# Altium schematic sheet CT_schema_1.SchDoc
size 515 x 463 mm
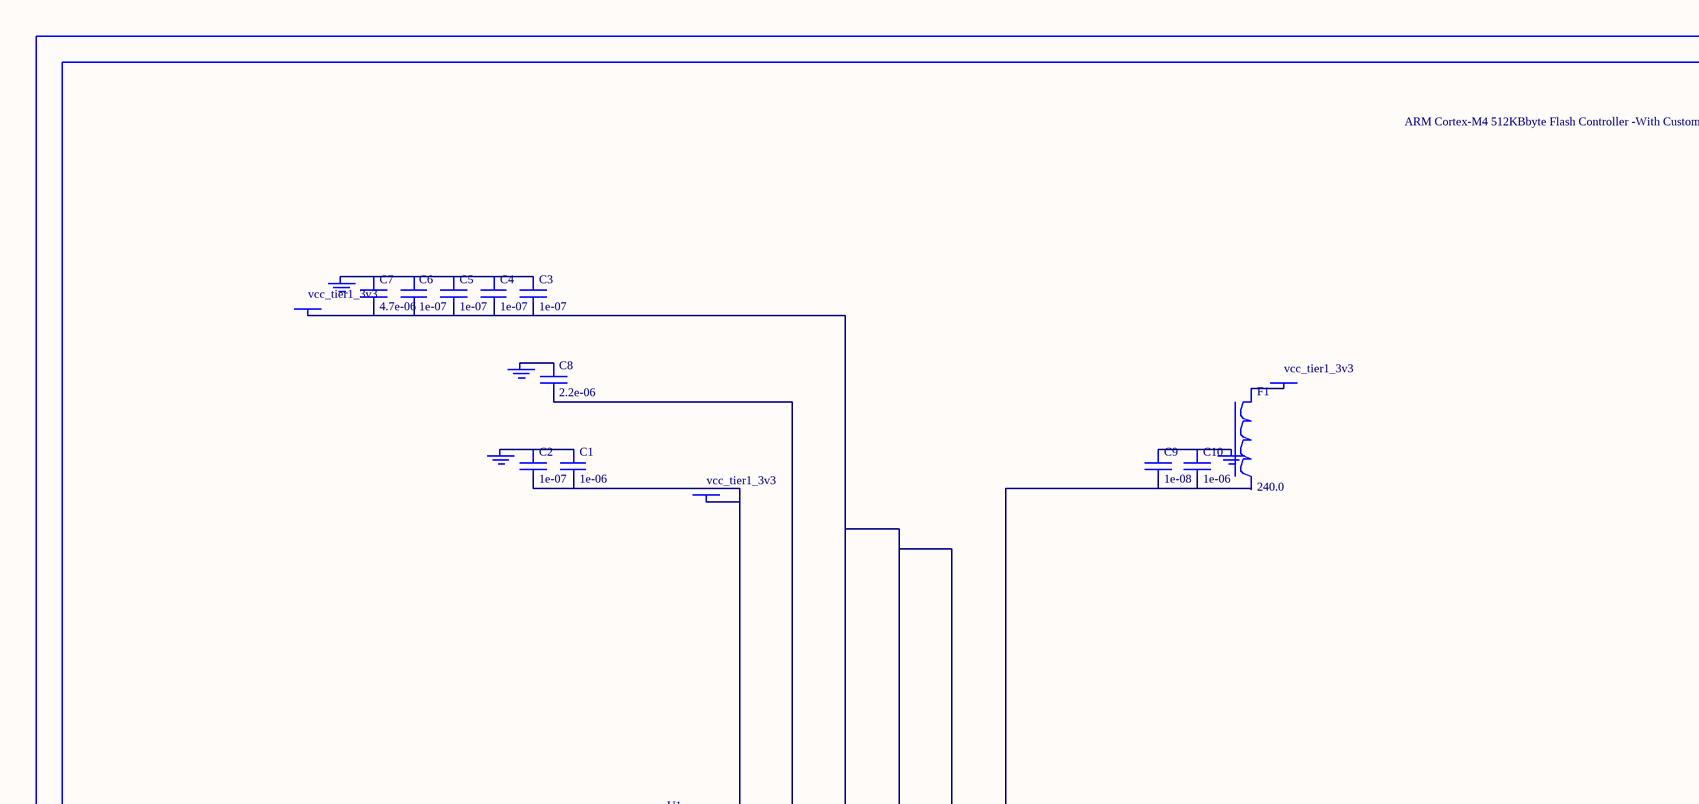
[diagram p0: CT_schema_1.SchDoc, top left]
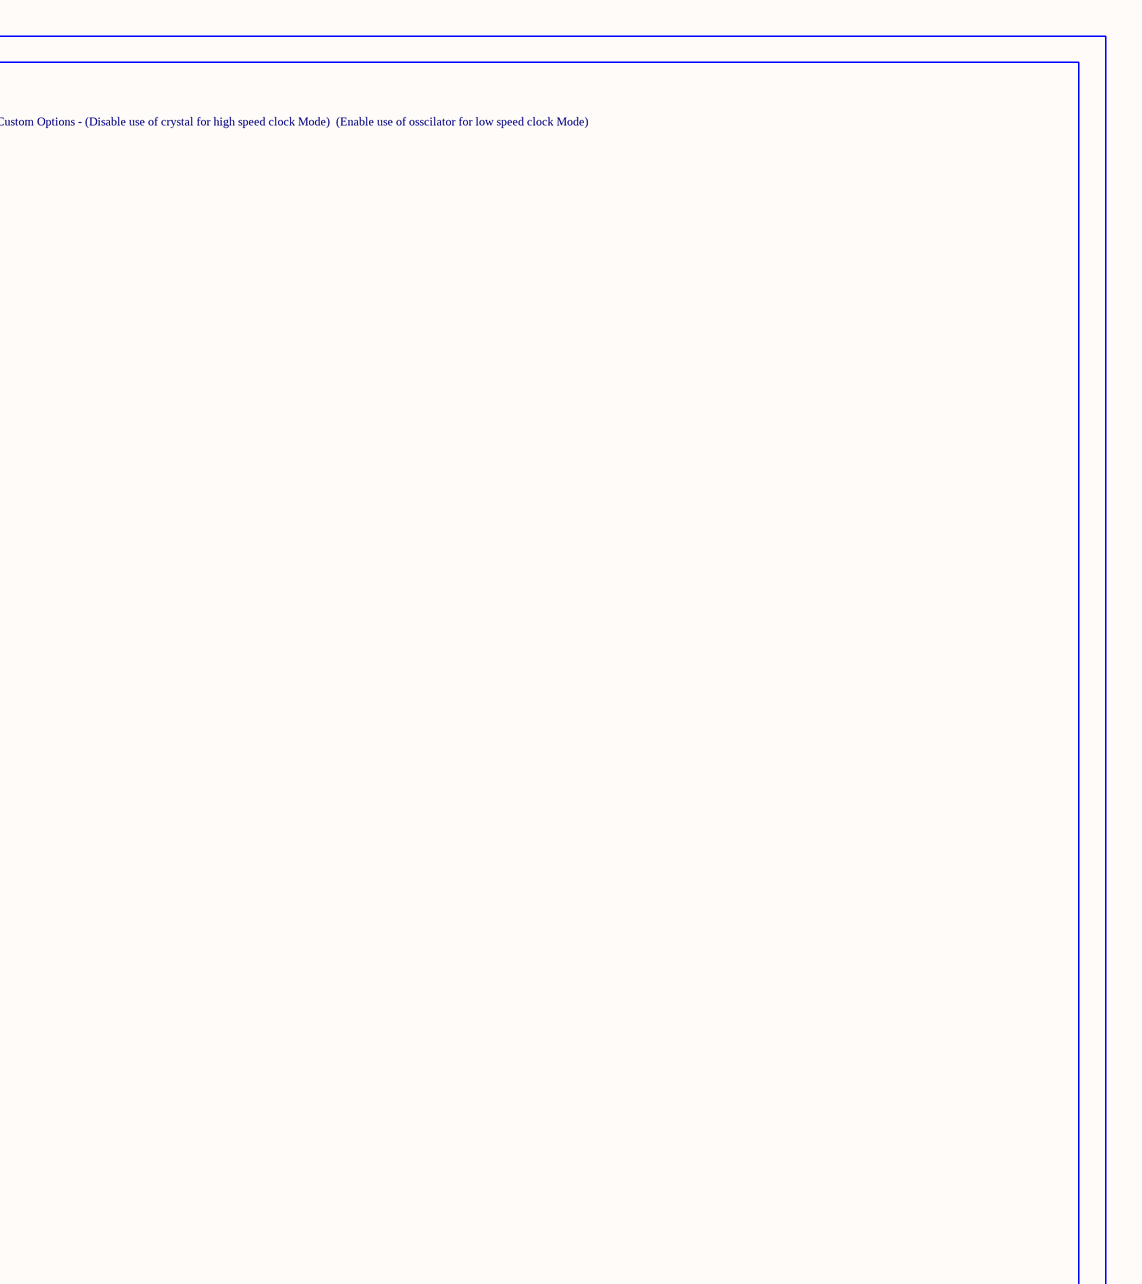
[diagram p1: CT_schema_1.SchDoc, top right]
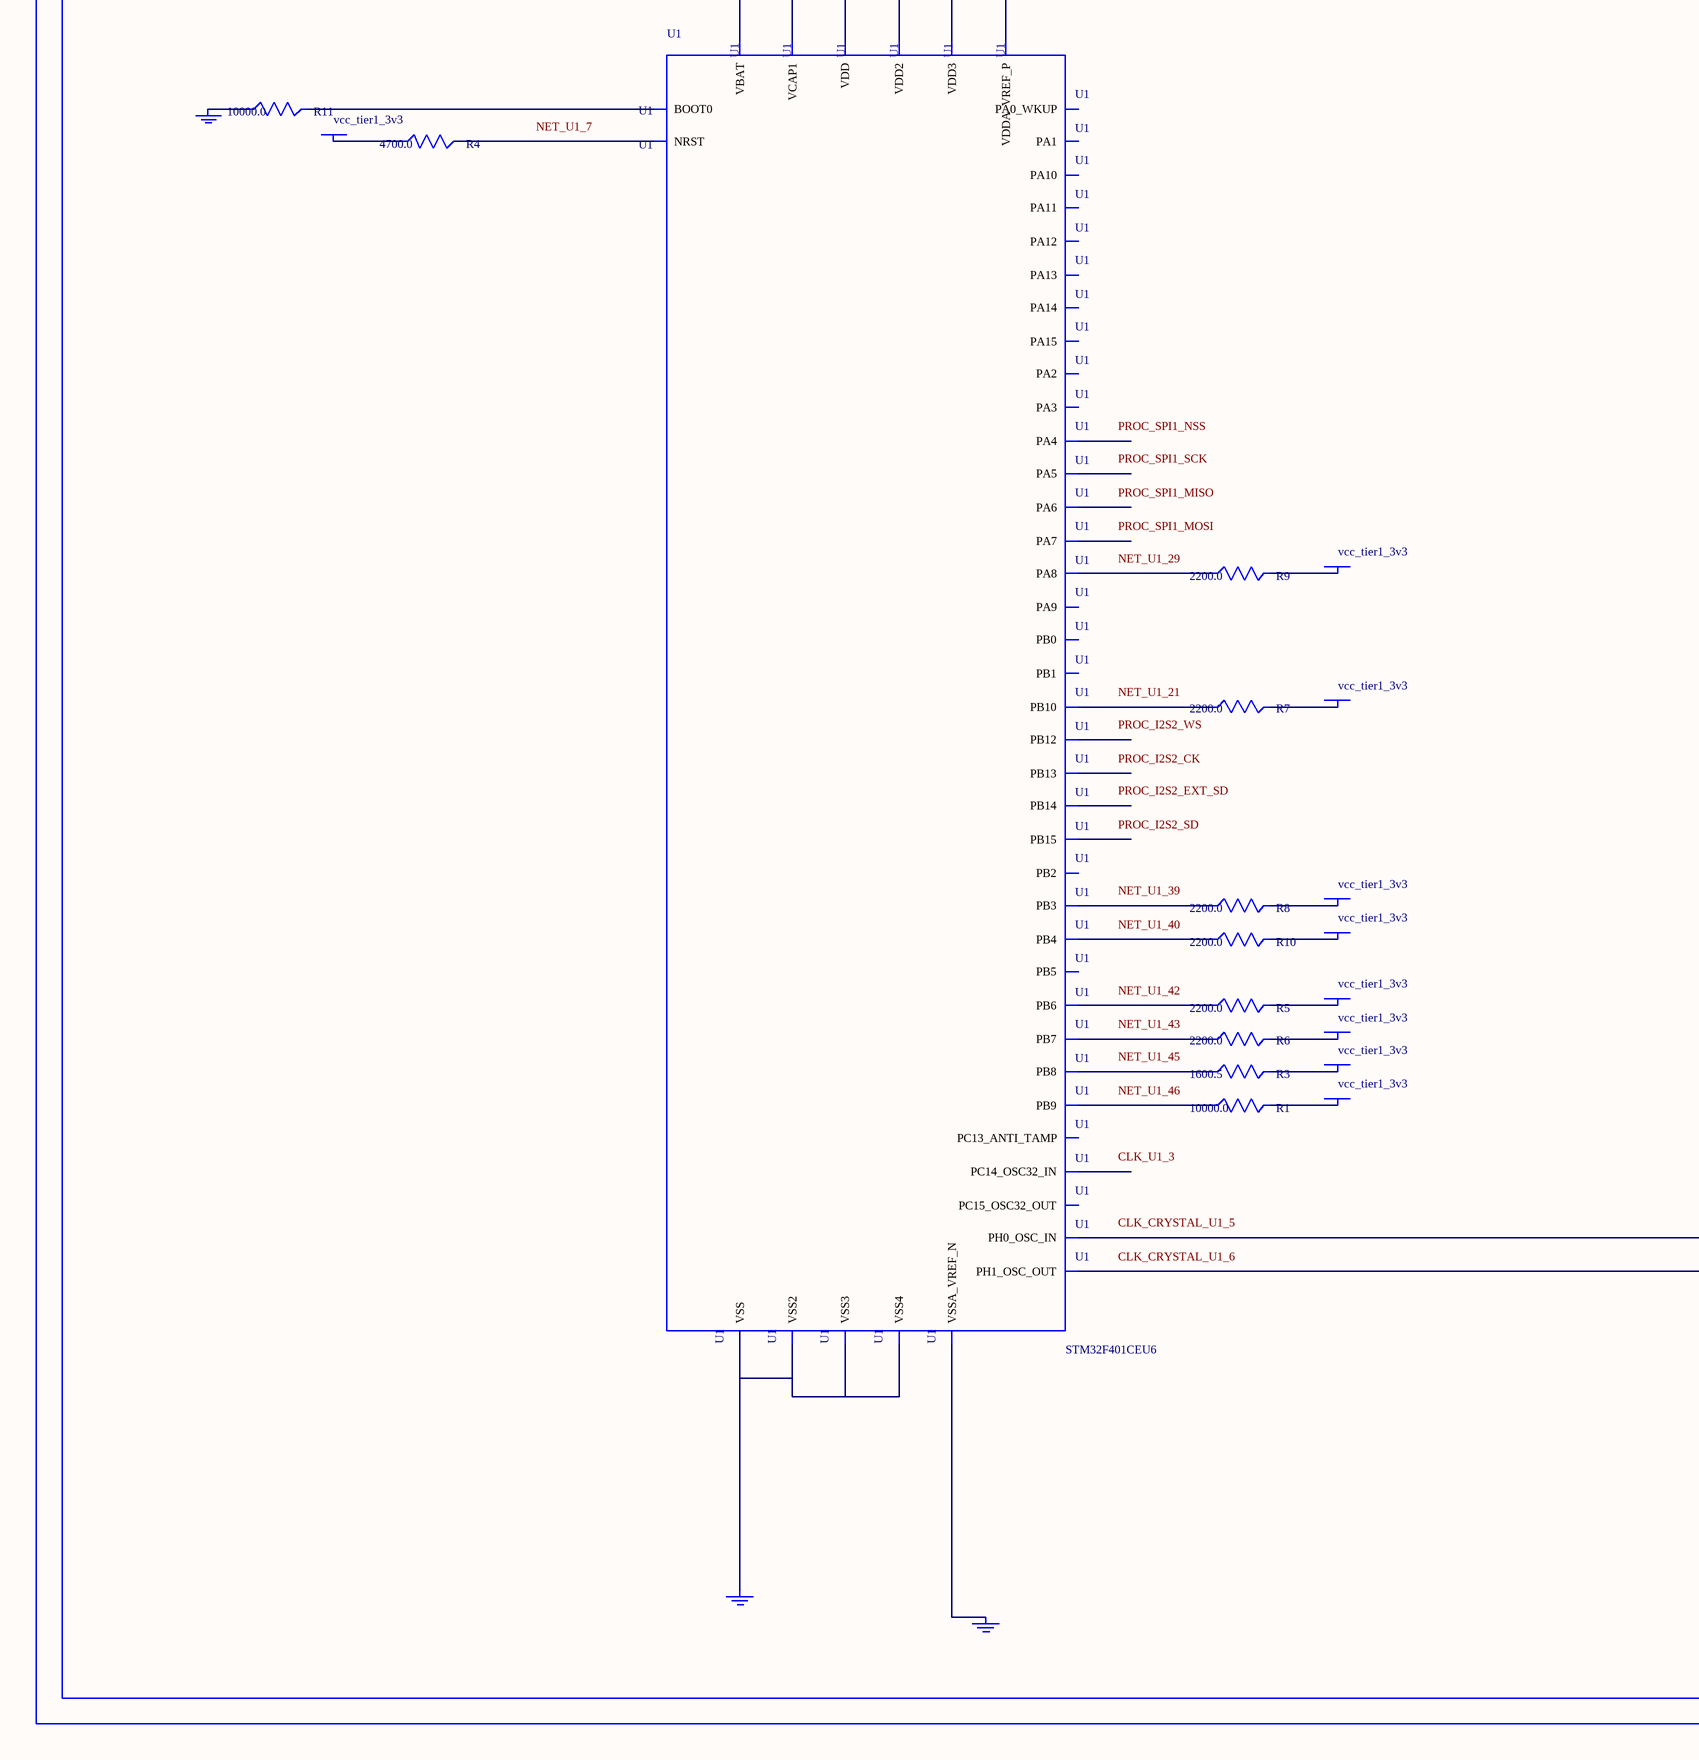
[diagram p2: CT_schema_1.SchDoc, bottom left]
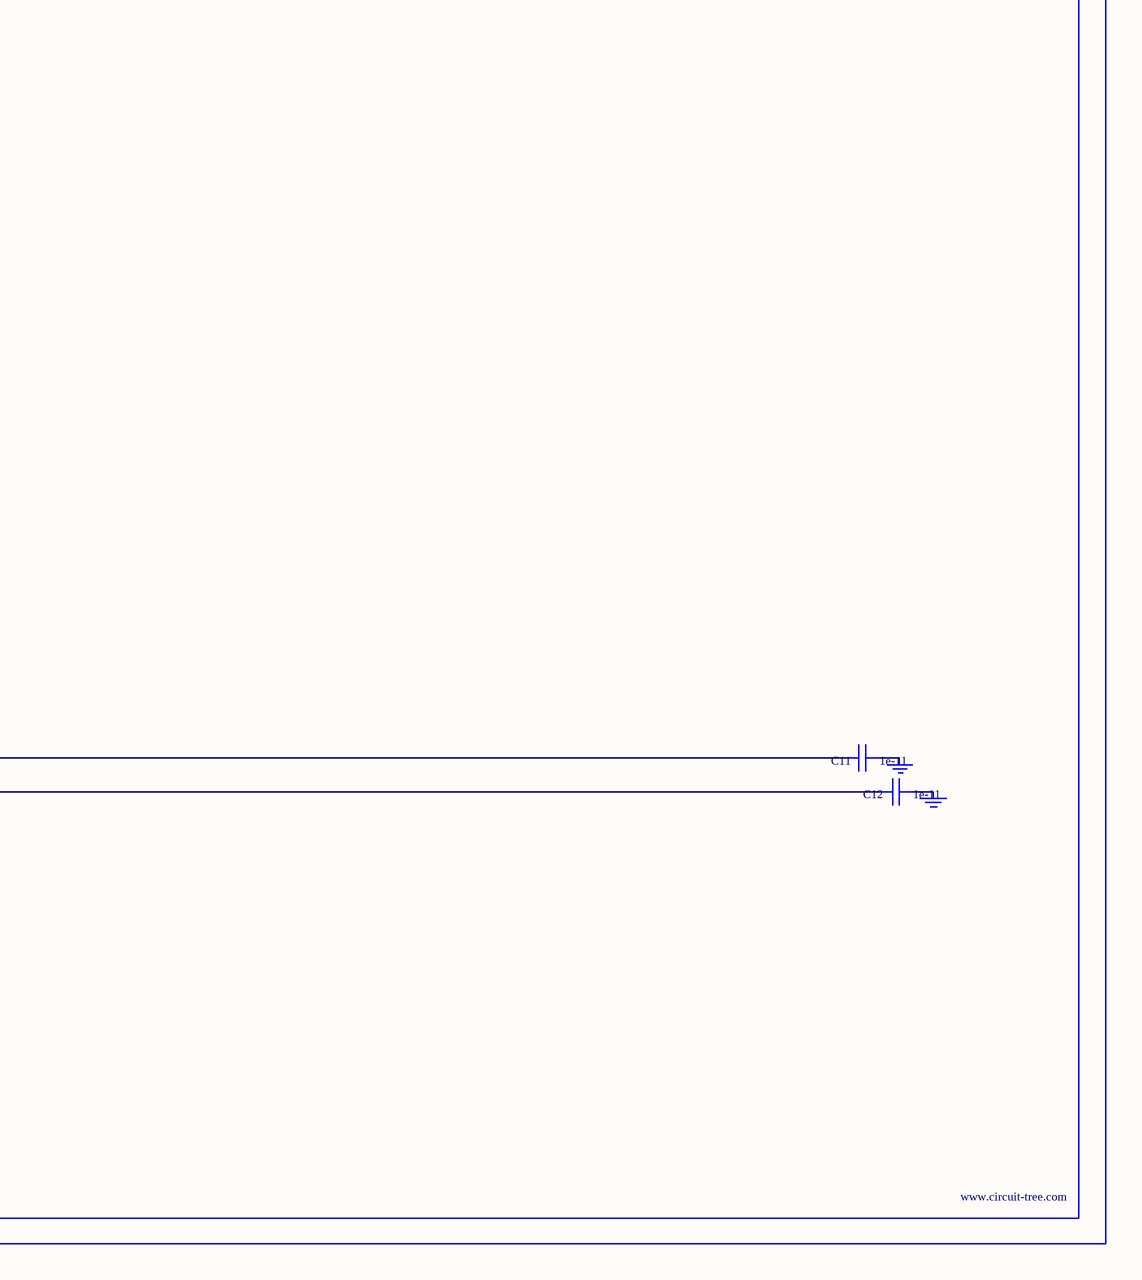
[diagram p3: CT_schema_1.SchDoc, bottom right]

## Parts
BORDER0  (no value)
C1  1e-06  [C0603]
C2  1e-07  [C0603]
C3  1e-07  [C0603]
C4  1e-07  [C0603]
C5  1e-07  [C0603]
C6  1e-07  [C0603]
C7  4.7e-06  [C0603]
C8  2.2e-06  [C0603]
C9  1e-08  [C0603]
C10  1e-06  [C0603]
C11  1e-11  [C0402]
C12  1e-11  [C0402]
F1  240.0  [L0603]
GND_INSTANCE_0_0  (no value)
GND_INSTANCE_0_1  (no value)
GND_INSTANCE_0_2  (no value)
GND_INSTANCE_0_3  (no value)
GND_INSTANCE_0_4  (no value)
GND_INSTANCE_0_5  (no value)
GND_INSTANCE_0_6  (no value)
GND_INSTANCE_0_7  (no value)
GND_INSTANCE_0_8  (no value)
POWER_INSTANCE_0_0  vcc_tier1_3v3
POWER_INSTANCE_0_1  vcc_tier1_3v3
POWER_INSTANCE_0_2  vcc_tier1_3v3
POWER_INSTANCE_0_3  vcc_tier1_3v3
POWER_INSTANCE_0_4  vcc_tier1_3v3
POWER_INSTANCE_0_5  vcc_tier1_3v3
POWER_INSTANCE_0_6  vcc_tier1_3v3
POWER_INSTANCE_0_7  vcc_tier1_3v3
POWER_INSTANCE_0_8  vcc_tier1_3v3
POWER_INSTANCE_0_9  vcc_tier1_3v3
POWER_INSTANCE_0_10  vcc_tier1_3v3
POWER_INSTANCE_0_11  vcc_tier1_3v3
R1  10000.0  [R0603]
R3  1600.5  [R0603]
R4  4700.0  [R0603]
R5  2200.0  [R0603]
R6  2200.0  [R0603]
R7  2200.0  [R0603]
R8  2200.0  [R0603]
R9  2200.0  [R0603]
R10  2200.0  [R0603]
R11  10000.0  [R0603]
U1  STM32F401CEU6  [UFQFPN48]

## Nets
NetC1_1: C1.1 C2.1 GND_INSTANCE_0_0.0(GND)
NetC1_2: C1.2 C2.2 POWER_INSTANCE_0_0.0(PWR) U1.1(VBAT)
NetC3_1: C3.1 C4.1 C5.1 C6.1 C7.1 GND_INSTANCE_0_6.0(GND)
NetC3_2: C3.2 C4.2 C5.2 C6.2 C7.2 POWER_INSTANCE_0_2.0(PWR) U1.24(VDD) U1.36(VDD2) U1.48(VDD3)
NetC8_1: C8.1 GND_INSTANCE_0_5.0(GND)
NetC8_2: C8.2 U1.22(VCAP1)
NetC9_1: C9.1 C10.1 GND_INSTANCE_0_4.0(GND)
NetC9_2: C9.2 C10.2 U1.9(VDDA_VREF_P)
NetC11_1: C11.1 GND_INSTANCE_0_1.0(GND)
NetC11_2: C11.2 U1.5(PH0_OSC_IN)
NetC12_1: C12.1 GND_INSTANCE_0_2.0(GND)
NetC12_2: C12.2 U1.6(PH1_OSC_OUT)
NetF1_1: F1.1 POWER_INSTANCE_0_1.0(PWR)
NetGND_INSTANCE_0_3_0: GND_INSTANCE_0_3.0(GND) U1.8(VSSA_VREF_N)
NetGND_INSTANCE_0_7_0: GND_INSTANCE_0_7.0(GND) R11.1
NetGND_INSTANCE_0_8_0: GND_INSTANCE_0_8.0(GND) U1.23(VSS) U1.35(VSS2) U1.47(VSS3) U1.49(VSS4)
NetPOWER_INSTANCE_0_3_0: POWER_INSTANCE_0_3.0(PWR) R4.1
NetPOWER_INSTANCE_0_4_0: POWER_INSTANCE_0_4.0(PWR) R7.2
NetPOWER_INSTANCE_0_5_0: POWER_INSTANCE_0_5.0(PWR) R9.2
NetPOWER_INSTANCE_0_6_0: POWER_INSTANCE_0_6.0(PWR) R8.2
NetPOWER_INSTANCE_0_7_0: POWER_INSTANCE_0_7.0(PWR) R10.2
NetPOWER_INSTANCE_0_8_0: POWER_INSTANCE_0_8.0(PWR) R5.2
NetPOWER_INSTANCE_0_9_0: POWER_INSTANCE_0_9.0(PWR) R6.2
NetPOWER_INSTANCE_0_10_0: POWER_INSTANCE_0_10.0(PWR) R3.2
NetPOWER_INSTANCE_0_11_0: POWER_INSTANCE_0_11.0(PWR) R1.2
NetR1_1: R1.1 U1.46(PB9)
NetR3_1: R3.1 U1.45(PB8)
NetR4_2: R4.2 U1.7(NRST)
NetR5_1: R5.1 U1.42(PB6)
NetR6_1: R6.1 U1.43(PB7)
NetR7_1: R7.1 U1.21(PB10)
NetR8_1: R8.1 U1.39(PB3)
NetR9_1: R9.1 U1.29(PA8)
NetR10_1: R10.1 U1.40(PB4)
NetR11_2: R11.2 U1.44(BOOT0)

Not connected (* = marked no-connect by the designer): F1 2; U1 2(PC13_ANTI_TAMP) 3(PC14_OSC32_IN) 4(PC15_OSC32_OUT) 10(PA0_WKUP) 11(PA1) 12(PA2) 13(PA3) 14(PA4) 15(PA5) 16(PA6) 17(PA7) 18(PB0) 19(PB1) 20(PB2) 25(PB12) 26(PB13) 27(PB14) 28(PB15) 30(PA9) 31(PA10) 32(PA11) 33(PA12) 34(PA13) 37(PA14) 38(PA15) 41(PB5)

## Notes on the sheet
- Labels drawn without touching a wire or pin: CLK_CRYSTAL_U1_5, CLK_CRYSTAL_U1_6, CLK_U1_3, NET_U1_7, NET_U1_21, NET_U1_29, NET_U1_39, NET_U1_40, NET_U1_42, NET_U1_43, NET_U1_45, NET_U1_46, PROC_I2S2_CK, PROC_I2S2_EXT_SD, PROC_I2S2_SD, PROC_I2S2_WS, PROC_SPI1_MISO, PROC_SPI1_MOSI, PROC_SPI1_NSS, PROC_SPI1_SCK

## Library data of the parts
BORDER0 = BORDER_PAGE0
C1 C10 = C0603C105K3RACTU
C2-C6 = 06035C104K4Z2A
C7 = GRM188R6YA475KE15D
C8 = C0603C225K8RACTU
C9 = 06035C103K4Z2A
C11 C12 = C0402C100K3GACTU
F1 = Z0603C241ASMST
GND_INSTANCE_0_0-GND_INSTANCE_0_8 = GND
POWER_INSTANCE_0_0-POWER_INSTANCE_0_11 = PWR
R1 R11 = RC0603JR-0710KL
R3 = R3
R4 = RC0603JR-074K7L
R5-R10 = RC0603JR-072K2L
